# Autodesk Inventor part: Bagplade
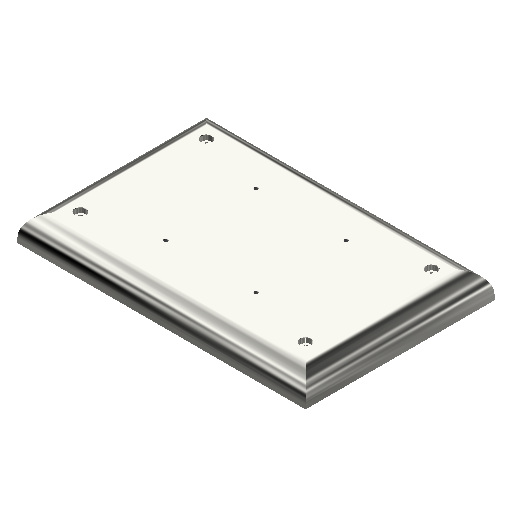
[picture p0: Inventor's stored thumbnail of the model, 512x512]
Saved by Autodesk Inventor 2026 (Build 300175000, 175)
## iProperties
Created: 2013-10
Part Number: Bagplade
Material: Aluminum 6061
Document SubType Name: Modeling
Designer: Lars Bertram Pedersen
Density: 2.7 g/cm^3
Appearance: Silver
Mass: 5056.38 g
Surface Area: 1581.89 cm^2
Volume: 1872.73 cm^3
Stock Number: 2001
Author: Lars Bertram Pedersen
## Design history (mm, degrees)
node "Blocks"
  sketch "udskæring"
    geometry: L1 (135.888, 95)-(135.888, 100); L2 (135.888, 100)-(127.888, 100); L3 (127.888, 100)-(127.888, 95); A1 r 4 centre (131.888, 95) between (127.888, 95) and (135.888, 95); 1 further point
    constraints: 6 end point, 2 point on circle, 2 tangent, 1 centre point, 1 coincident, 1 perpendicular
    dimensions: "d12" = 8 diameter of A1; "d13" = 9 dimension on A1 L2
sketch "Sketch1"
  geometry: L1 (160, -105)-(-160, -105); L2 (-160, -105)-(-160, 105); L3 (-160, 105)-(160, 105); L4 (160, 105)-(160, -105); L5 (160, -105)-(-160, 105); L6 (-160, -105)-(160, 105); 3 further points
  constraints: 12 end point, 3 midpoint, 2 parallel, 1 coincident, 1 horizontal, 1 perpendicular
  dimensions: "d0" = 320 distance of L2.end L3.end; "d1" = 210 distance of L1.end L2.end
extrude "Extrusion1" new body sketch "Sketch1" stored distance "d2" = 30; taper "d3" = 0 deg
fillet "Fillet1" dims "d6" = 25
sketch "Sketch9"
  geometry: L1 (50, -50)-(-50, -50); L2 (-50, -50)-(-50, 50); L3 (-50, 50)-(50, 50); L4 (50, 50)-(50, -50); L5 (50, -50)-(-50, 50); L6 (-50, -50)-(50, 50); 5 further points
  constraints: 12 end point, 4 coincident, 2 midpoint, 2 parallel, 1 horizontal, 1 perpendicular
  dimensions: "d53" = 100 distance of L2.end L3.end; "d54" = 100 distance of L3.end L1.start
hole "Hole3" sketch "Sketch9" diameter "d55" = 4.134; stored, may be unused: countersink angle "d59" = 82 deg, drill point angle "d61" = 118 deg; dims "d56" = 17.5, "d57" = 3.023, "d58" = 2, "d60" = 22.5
sketch "Sketch10"
  geometry: L1 (160, 105)-(-160, 105) reference; L2 (-160, 105)-(-160, -105) reference; L3 (160, -105)-(160, 105) reference; L4 (-160, -105)-(160, -105) reference; 5 further points
  constraints: 2 horizontal alignment, 2 vertical alignment
  dimensions: "d67" = 35 distance from line of L1 point (-125, 70); "d68" = 35 distance from line of L2 point (-125, 70); "d69" = 35 distance from line of L4 point (-125, -70); "d70" = 35 distance from line of L3 point (125, 70)
hole "Hole4" sketch "Sketch10" diameter "d71" = 6.6; stored, may be unused: countersink angle "d75" = 90 deg, drill point angle "d77" = 118 deg; dims "d72" = 16, "d73" = 12, "d74" = 5.5, "d76" = 16
chamfer "Chamfer1" distance "d78" = 0.3; stored, may be unused: second distance "d79" = 2, angle "d80" = 45 deg
feature "ī耀ĭ耀į耀ı耀ĳ耀ĵ耀ķ耀Ĺ耀" dims "d0" = 320, "d1" = 210, "d2" = 30, "d3" = 0, "d6" = 25, "d12" = 8, "d13" = 9, "d53" = 100, "d54" = 100, "d55" = 4.134, "d56" = 17.5, "d57" = 3.023, "d58" = 2, "d59" = 82 deg, "d60" = 22.5, "d61" = 118 deg, "d67" = 35, "d68" = 35, "d69" = 35, "d70" = 35, "d71" = 6.6, "d72" = 16, "d73" = 12, "d74" = 5.5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
body "Solid1"
